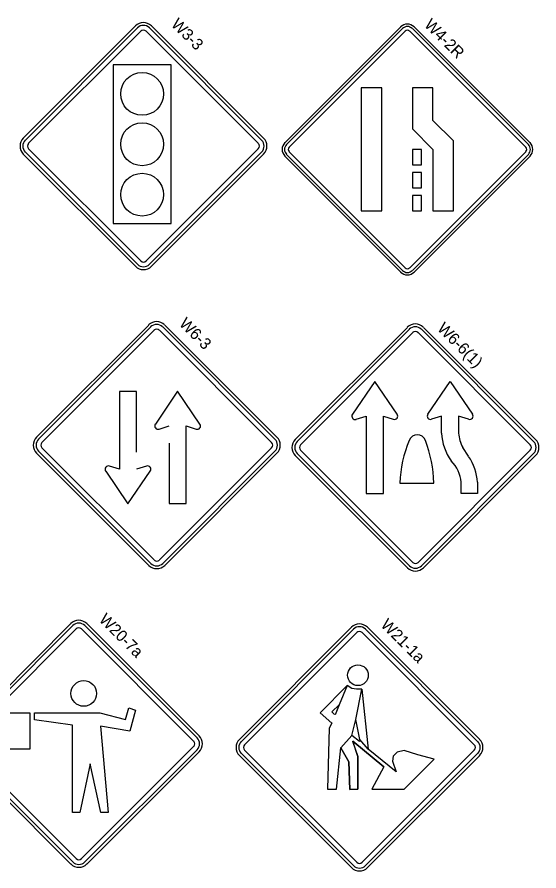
# Model space of a CAD drawing. Extents: x 1531.44 to 1538.58, y 1529.59 to 1539.3.
# Drawn here: x 1535.575 to 1538.294, y 1534.329 to 1538.777 of the extents above; entities that cross this region are included whole.
import ezdxf

# ---------------------------------------------------------------- set-up
doc = ezdxf.new("R2010")
doc.units = 0
for name, color, linetype in [('DETL-LINE', 7, 'Continuous'), ('DETL-NOTE', 7, 'Continuous'), ('SIGN-FACE_E', 7, 'Continuous')]:
    doc.layers.add(name, color=color, linetype=linetype)

msp = doc.modelspace()

# ---------------------------------------------------------------- linework, layer by layer
at = {"layer": 'DETL-LINE'}
for p, q in [((1536.1918, 1538.7309), (1535.6075, 1538.1466)), ((1536.2024, 1538.7212), (1535.618, 1538.136)), ((1536.8492, 1538.136), (1536.2648, 1538.7212)), ((1536.8597, 1538.1466), (1536.2754, 1538.7309)), ((1535.6348, 1538.1193), (1536.22, 1538.7036)), ((1536.2468, 1538.7036), (1536.2472, 1538.7036)), ((1536.8316, 1538.1193), (1536.2472, 1538.7036)), ((1536.2472, 1538.7036), (1536.8316, 1538.1193)), ((1536.2472, 1538.7036), (1536.8316, 1538.1193)), ((1536.377, 1538.5276), (1536.0752, 1538.5276)), ((1536.0752, 1538.5276), (1536.0752, 1537.701)), ((1536.377, 1537.701), (1536.377, 1538.5276)), ((1535.6075, 1538.063), (1536.1918, 1537.4786)), ((1535.618, 1538.0735), (1536.2024, 1537.4892)), ((1536.22, 1537.5068), (1535.6348, 1538.0911)), ((1536.8316, 1538.0911), (1536.2472, 1537.5068)), ((1536.2648, 1537.4892), (1536.8492, 1538.0735)), ((1536.2754, 1537.4786), (1536.8597, 1538.063)), ((1536.0752, 1537.701), (1536.377, 1537.701)), ((1536.2612, 1537.1726), (1535.6768, 1536.5883)), ((1536.2717, 1537.163), (1535.6874, 1536.5778)), ((1536.9185, 1536.5778), (1536.3342, 1537.163)), ((1536.9291, 1536.5883), (1536.3448, 1537.1726)), ((1535.7041, 1536.561), (1536.2893, 1537.1454)), ((1536.3162, 1537.1453), (1536.3166, 1537.1454)), ((1536.9009, 1536.561), (1536.3166, 1537.1454)), ((1536.3166, 1537.1454), (1536.9009, 1536.561)), ((1536.3166, 1537.1454), (1536.9009, 1536.561)), ((1537.609, 1537.1604), (1537.0246, 1536.5761)), ((1537.6195, 1537.1507), (1537.0352, 1536.5655)), ((1537.0519, 1536.5488), (1537.6371, 1537.1331)), ((1537.664, 1537.1331), (1537.6644, 1537.1331)), ((1538.2487, 1536.5488), (1537.6644, 1537.1331)), ((1537.6644, 1537.1331), (1538.2487, 1536.5488)), ((1537.6644, 1537.1331), (1538.2487, 1536.5488)), ((1538.2663, 1536.5655), (1537.682, 1537.1507)), ((1538.2769, 1536.5761), (1537.6926, 1537.1604)), ((1537.4385, 1536.8785), (1537.3223, 1536.7078)), ((1537.5555, 1536.7078), (1537.4385, 1536.8785)), ((1537.7148, 1536.7078), (1537.831, 1536.8785)), ((1537.831, 1536.8785), (1537.948, 1536.7078)), ((1536.1079, 1536.8257), (1536.1079, 1536.5107)), ((1536.1977, 1536.8257), (1536.1079, 1536.8257)), ((1536.1977, 1536.5107), (1536.1977, 1536.8257)), ((1536.4115, 1536.8275), (1536.2954, 1536.6568)), ((1536.5277, 1536.6568), (1536.4115, 1536.8275)), ((1537.3426, 1536.6814), (1537.3945, 1536.6981)), ((1537.3945, 1536.6981), (1537.3945, 1536.6092)), ((1537.4834, 1536.6981), (1537.5353, 1536.6814)), ((1537.4834, 1536.6092), (1537.4834, 1536.6981)), ((1537.787, 1536.6981), (1537.735, 1536.6814)), ((1537.787, 1536.6092), (1537.787, 1536.6981)), ((1537.9278, 1536.6814), (1537.8758, 1536.6981)), ((1537.8758, 1536.6981), (1537.8758, 1536.6092)), ((1536.3147, 1536.6304), (1536.3666, 1536.6471)), ((1536.4564, 1536.5573), (1536.4564, 1536.6471)), ((1536.4564, 1536.6471), (1536.5083, 1536.6304)), ((1537.3945, 1536.6092), (1537.3945, 1536.2942)), ((1537.4834, 1536.2942), (1537.4834, 1536.6092)), ((1536.3666, 1536.5573), (1536.3666, 1536.2423)), ((1536.4564, 1536.2423), (1536.4564, 1536.5573)), ((1535.6768, 1536.5047), (1536.2612, 1535.9204)), ((1535.6874, 1536.5153), (1536.2717, 1535.931)), ((1536.2893, 1535.9486), (1535.7041, 1536.5329)), ((1536.1079, 1536.5107), (1536.1079, 1536.4209)), ((1536.9009, 1536.5329), (1536.3166, 1535.9486)), ((1536.3342, 1535.931), (1536.9185, 1536.5153)), ((1536.3448, 1535.9204), (1536.9291, 1536.5047)), ((1537.0352, 1536.503), (1537.6195, 1535.9187)), ((1537.6371, 1535.9363), (1537.0519, 1536.5206)), ((1538.2487, 1536.5206), (1537.6644, 1535.9363)), ((1537.682, 1535.9187), (1538.2663, 1536.503)), ((1537.9278, 1536.4887), (1537.8978, 1536.5353)), ((1537.0246, 1536.4925), (1537.609, 1535.9082)), ((1537.6926, 1535.9082), (1538.2769, 1536.4925)), ((1536.0366, 1536.4112), (1536.1528, 1536.2405)), ((1536.1079, 1536.4209), (1536.056, 1536.4376)), ((1536.1528, 1536.2405), (1536.269, 1536.4112)), ((1536.2496, 1536.4376), (1536.1977, 1536.4209)), ((1537.5687, 1536.3488), (1537.7465, 1536.3488)), ((1537.889, 1536.2951), (1537.889, 1536.3532)), ((1537.9744, 1536.3532), (1537.9744, 1536.2951)), ((1537.3945, 1536.2942), (1537.4834, 1536.2942)), ((1537.9744, 1536.2951), (1537.889, 1536.2951)), ((1536.3666, 1536.2423), (1536.4564, 1536.2423)), ((1535.8551, 1535.6169), (1535.2708, 1535.0326)), ((1535.8657, 1535.6072), (1535.2814, 1535.022)), ((1536.5125, 1535.022), (1535.9282, 1535.6072)), ((1536.523, 1535.0326), (1535.9387, 1535.6169)), ((1535.2981, 1535.0053), (1535.8833, 1535.5896)), ((1535.9101, 1535.5896), (1535.9106, 1535.5896)), ((1536.4949, 1535.0053), (1535.9106, 1535.5896)), ((1535.9106, 1535.5896), (1536.4949, 1535.0053)), ((1535.9106, 1535.5896), (1536.4949, 1535.0053)), ((1537.3175, 1535.598), (1536.7332, 1535.0136)), ((1537.328, 1535.5883), (1536.7437, 1535.0031)), ((1536.7604, 1534.9864), (1537.3456, 1535.5707)), ((1537.3725, 1535.5706), (1537.3729, 1535.5707)), ((1537.9572, 1534.9864), (1537.3729, 1535.5707)), ((1537.3729, 1535.5707), (1537.9572, 1534.9864)), ((1537.3729, 1535.5707), (1537.9572, 1534.9864)), ((1537.9748, 1535.0031), (1537.3905, 1535.5883)), ((1537.9854, 1535.0136), (1537.4011, 1535.598)), ((1537.1547, 1535.1524), (1537.2942, 1535.295)), ((1537.1547, 1535.1524), (1537.2942, 1535.295)), ((1537.2942, 1535.295), (1537.2535, 1535.1934)), ((1537.3194, 1535.2788), (1537.2942, 1535.295)), ((1537.344, 1535.2751), (1537.3194, 1535.2788)), ((1537.3406, 1535.117), (1537.3716, 1535.2751)), ((1537.3406, 1535.117), (1537.3716, 1535.2751)), ((1537.3716, 1535.2751), (1537.344, 1535.2751)), ((1537.3716, 1535.2751), (1537.4052, 1534.9634)), ((1536.1398, 1535.1174), (1536.1564, 1535.1781)), ((1536.1398, 1535.1174), (1536.1564, 1535.1781)), ((1536.1564, 1535.1781), (1536.1919, 1535.1655)), ((1536.1564, 1535.1781), (1536.1919, 1535.1655)), ((1536.1919, 1535.1655), (1536.1622, 1535.0562)), ((1536.1919, 1535.1655), (1536.1622, 1535.0562)), ((1537.2535, 1535.1934), (1537.2148, 1535.1569)), ((1537.2148, 1535.1569), (1537.2535, 1535.1934)), ((1537.2535, 1535.1934), (1537.2148, 1535.1569)), ((1537.2535, 1535.1934), (1537.2322, 1535.1414)), ((1535.4896, 1535.1523), (1535.6407, 1535.1523)), ((1535.6407, 1535.1523), (1535.6407, 1534.9628)), ((1535.6658, 1535.1151), (1535.6658, 1535.1529)), ((1535.6658, 1535.1529), (1536.0065, 1535.1529)), ((1535.6658, 1535.1529), (1536.0065, 1535.1529)), ((1535.6658, 1535.1151), (1535.6658, 1535.1529)), ((1535.8634, 1535.0876), (1535.6658, 1535.1151)), ((1535.8634, 1535.0876), (1535.6658, 1535.1151)), ((1536.0065, 1535.1529), (1536.1398, 1535.1174)), ((1536.0065, 1535.1529), (1536.1398, 1535.1174)), ((1537.1547, 1535.1524), (1537.2154, 1535.0981)), ((1537.229, 1535.1433), (1537.2148, 1535.1569)), ((1537.3194, 1535.0343), (1537.3406, 1535.117)), ((1537.3616, 1535.0136), (1537.3406, 1535.117)), ((1535.8634, 1534.6337), (1535.8634, 1535.0876)), ((1535.8634, 1534.6337), (1535.8634, 1535.0876)), ((1536.1622, 1535.0562), (1536.0099, 1535.0831)), ((1536.0099, 1535.0831), (1536.05, 1534.6337)), ((1536.1622, 1535.0562), (1536.0099, 1535.0831)), ((1536.0099, 1535.0831), (1536.05, 1534.6337)), ((1537.3596, 1535.0025), (1537.3194, 1535.0343)), ((1537.4856, 1534.8704), (1537.3236, 1535.0054)), ((1537.3616, 1535.0136), (1537.3596, 1535.0025)), ((1535.2708, 1534.949), (1535.8551, 1534.3646)), ((1535.2814, 1534.9595), (1535.8657, 1534.3752)), ((1535.8833, 1534.3928), (1535.2981, 1534.9771)), ((1535.6407, 1534.9628), (1535.4896, 1534.9628)), ((1536.4949, 1534.9771), (1535.9106, 1534.3928)), ((1535.9282, 1534.3752), (1536.5125, 1534.9595)), ((1535.9387, 1534.3646), (1536.523, 1534.949)), ((1536.7437, 1534.9406), (1537.328, 1534.3563)), ((1537.3456, 1534.3739), (1536.7604, 1534.9582)), ((1537.2398, 1534.7541), (1537.2621, 1534.9694)), ((1537.9572, 1534.9582), (1537.3729, 1534.3739)), ((1537.3905, 1534.3563), (1537.9748, 1534.9406)), ((1537.5497, 1534.8444), (1537.4052, 1534.9634)), ((1537.5549, 1534.9474), (1537.535, 1534.9264)), ((1537.5927, 1534.9552), (1537.5549, 1534.9474)), ((1537.6639, 1534.9337), (1537.5927, 1534.9552)), ((1536.7332, 1534.93), (1537.3175, 1534.3457)), ((1537.4011, 1534.3457), (1537.9854, 1534.93)), ((1537.535, 1534.9264), (1537.5313, 1534.9001)), ((1537.5313, 1534.9001), (1537.5497, 1534.8444)), ((1537.5927, 1534.7546), (1537.7476, 1534.9111)), ((1537.7476, 1534.9111), (1537.6639, 1534.9337)), ((1535.9566, 1534.8867), (1535.9011, 1534.6337)), ((1535.9566, 1534.8867), (1535.9011, 1534.6337)), ((1536.0122, 1534.6337), (1535.9566, 1534.8867)), ((1536.0122, 1534.6337), (1535.9566, 1534.8867)), ((1537.4856, 1534.8704), (1537.4234, 1534.7541)), ((1537.4234, 1534.7541), (1537.5927, 1534.7546)), ((1535.9011, 1534.6337), (1535.8634, 1534.6337)), ((1535.9011, 1534.6337), (1535.8634, 1534.6337)), ((1536.05, 1534.6337), (1536.0122, 1534.6337)), ((1536.05, 1534.6337), (1536.0122, 1534.6337))]:
    msp.add_line(p, q, dxfattribs=at)
for points in [[(1537.2154, 1535.0999), (1537.2141, 1535.0957), (1537.201, 1535.0732), (1537.1928, 1534.7541), (1537.2398, 1534.7541)], [(1537.4052, 1534.9634), (1537.3616, 1535.0136), (1537.3606, 1535.008), (1537.3596, 1535.0025), (1537.3194, 1535.0343), (1537.2621, 1534.9694), (1537.3036, 1534.8972), (1537.3081, 1534.753), (1537.3501, 1534.7541), (1537.3509, 1534.9243), (1537.3236, 1535.0054), (1537.4856, 1534.8704)], [(1537.3222, 1535.0046), (1537.3509, 1534.9243), (1537.3501, 1534.7541), (1537.3081, 1534.753), (1537.3036, 1534.8972), (1537.2621, 1534.9694), (1537.2621, 1534.972)]]:
    msp.add_lwpolyline(points, dxfattribs=at)
for centre, radius in [((1536.2262, 1538.3766), 0.1115), ((1536.2262, 1538.1142), 0.1115), ((1536.2262, 1537.8518), 0.1115), ((1537.3512, 1535.3482), 0.0539), ((1535.9223, 1535.2531), 0.0668)]:
    msp.add_circle(centre, radius, dxfattribs=at)
for centre, radius, start, end in [((1536.2329, 1538.6896), 0.059, 45, 135), ((1536.2329, 1538.6896), 0.0443, 45, 135), ((1536.2329, 1538.6896), 0.0197, 45, 135), ((1535.6492, 1538.1048), 0.059, 135, 225), ((1536.8179, 1538.1051), 0.059, 315, 45), ((1535.649, 1538.1051), 0.0443, 135, 225), ((1535.649, 1538.1051), 0.0197, 135, 225), ((1536.8179, 1538.1051), 0.0197, 315, 45), ((1536.8179, 1538.1051), 0.0443, 315, 45), ((1536.2335, 1537.5206), 0.059, 225, 315), ((1536.2335, 1537.5206), 0.0443, 225, 315), ((1536.2335, 1537.5206), 0.0197, 225, 315), ((1536.3022, 1537.1314), 0.059, 45, 135), ((1536.3022, 1537.1314), 0.0443, 45, 135), ((1537.65, 1537.1192), 0.059, 45, 135), ((1537.65, 1537.1192), 0.0443, 45, 135), ((1536.3022, 1537.1314), 0.0197, 45, 135), ((1537.65, 1537.1192), 0.0197, 45, 135), ((1537.3368, 1536.6979), 0.0175, 145.7397, 288), ((1537.5407, 1536.6981), 0.0175, 252, 34.2603), ((1537.7295, 1536.6981), 0.0175, 145.7397, 288), ((1537.9332, 1536.6981), 0.0175, 252, 34.2603), ((1536.3097, 1536.6468), 0.0175, 145.7397, 288), ((1536.5134, 1536.6468), 0.0175, 252, 34.2603), ((1535.7186, 1536.5466), 0.059, 135, 225), ((1536.8873, 1536.5468), 0.059, 315, 45), ((1537.6605, 1536.5564), 0.0446, 20.3641, 159.6359), ((1538.0539, 1536.6209), 0.2674, 182.5554, 215.8093), ((1538.0539, 1536.6209), 0.1784, 183.8322, 208.8162), ((1535.7184, 1536.5468), 0.0443, 135, 225), ((1535.7184, 1536.5468), 0.0197, 135, 225), ((1536.8873, 1536.5468), 0.0197, 315, 45), ((1536.8873, 1536.5468), 0.0443, 315, 45), ((1537.0664, 1536.5344), 0.059, 135, 225), ((1537.0662, 1536.5346), 0.0443, 135, 225), ((1537.0662, 1536.5346), 0.0197, 135, 225), ((1538.2363, 1536.3159), 0.6685, 157.4833, 177.1559), ((1537.0786, 1536.3313), 0.6685, 1.524, 21.0959), ((1538.2351, 1536.5346), 0.0197, 315, 45), ((1538.2351, 1536.5346), 0.0443, 315, 45), ((1538.2351, 1536.5346), 0.059, 315, 45), ((1537.7097, 1536.3377), 0.1797, 4.968, 44.8693), ((1537.7097, 1536.3377), 0.265, 3.3657, 34.6128), ((1536.0509, 1536.4212), 0.0175, 72, 214.2603), ((1536.2547, 1536.4212), 0.0175, 325.7397, 108), ((1536.3028, 1535.9624), 0.059, 225, 315), ((1536.3028, 1535.9624), 0.0443, 225, 315), ((1536.3028, 1535.9624), 0.0197, 225, 315), ((1537.6506, 1535.9501), 0.0443, 225, 315), ((1537.6506, 1535.9501), 0.0197, 225, 315), ((1537.6506, 1535.9501), 0.059, 225, 315), ((1535.8962, 1535.5756), 0.059, 45, 135), ((1535.8962, 1535.5756), 0.0443, 45, 135), ((1537.3586, 1535.5567), 0.059, 45, 135), ((1535.8962, 1535.5756), 0.0197, 45, 135), ((1537.3586, 1535.5567), 0.0443, 45, 135), ((1537.3586, 1535.5567), 0.0197, 45, 135), ((1536.4813, 1534.9911), 0.059, 315, 45), ((1536.4813, 1534.9911), 0.0197, 315, 45), ((1536.4813, 1534.9911), 0.0443, 315, 45), ((1536.7749, 1534.9719), 0.059, 135, 225), ((1536.7747, 1534.9722), 0.0443, 135, 225), ((1536.7747, 1534.9722), 0.0197, 135, 225), ((1537.9436, 1534.9722), 0.0197, 315, 45), ((1537.9436, 1534.9722), 0.0443, 315, 45), ((1537.9436, 1534.9722), 0.059, 315, 45), ((1535.8968, 1534.4066), 0.059, 225, 315), ((1535.8968, 1534.4066), 0.0443, 225, 315), ((1535.8968, 1534.4066), 0.0197, 225, 315), ((1537.3592, 1534.3877), 0.0197, 225, 315), ((1537.3592, 1534.3877), 0.059, 225, 315), ((1537.3592, 1534.3877), 0.0443, 225, 315)]:
    msp.add_arc(centre, radius, start, end, dxfattribs=at)
at = {"layer": 'SIGN-FACE_E'}
for p, q in [((1536.9705, 1538.1226), (1537.5737, 1538.7258)), ((1537.6435, 1538.7258), (1538.248, 1538.1226)), ((1536.9794, 1538.1137), (1537.5826, 1538.7169)), ((1536.9934, 1538.0998), (1537.5965, 1538.703)), ((1537.6207, 1538.703), (1538.2251, 1538.0998)), ((1537.6346, 1538.7169), (1538.2391, 1538.1137)), ((1537.5737, 1537.4484), (1536.9705, 1538.0528)), ((1537.5826, 1537.4572), (1536.9794, 1538.0617)), ((1537.5965, 1537.4712), (1536.9934, 1538.0757)), ((1538.2251, 1538.0757), (1537.6207, 1537.4712)), ((1538.2391, 1538.0617), (1537.6346, 1537.4572)), ((1538.248, 1538.0528), (1537.6435, 1537.4484))]:
    msp.add_line(p, q, dxfattribs=at)
for points in [[(1537.4753, 1538.4077), (1537.3686, 1538.4077), (1537.3686, 1537.7677), (1537.4753, 1537.7677), (1537.4753, 1538.4077)], [(1537.8486, 1538.1319), (1537.7419, 1538.2386), (1537.7419, 1538.4077), (1537.6353, 1538.4077), (1537.6353, 1538.1944), (1537.7419, 1538.0877), (1537.7419, 1537.7677), (1537.8486, 1537.7677), (1537.8486, 1538.1319)], [(1537.6353, 1538.0077), (1537.6819, 1538.0077), (1537.6819, 1538.0877), (1537.6353, 1538.0877), (1537.6353, 1538.0077)], [(1537.6353, 1537.8877), (1537.6819, 1537.8877), (1537.6819, 1537.9677), (1537.6353, 1537.9677), (1537.6353, 1537.8877)], [(1537.6353, 1537.7677), (1537.6819, 1537.7677), (1537.6819, 1537.8477), (1537.6353, 1537.8477), (1537.6353, 1537.7677)]]:
    msp.add_lwpolyline(points, dxfattribs=at)
for centre, radius, start, end in [((1537.6086, 1538.6906), 0.0496, 45.06, 135), ((1537.6086, 1538.6913), 0.0365, 45.06, 135), ((1537.6086, 1538.6916), 0.0165, 45.06, 135), ((1537.0057, 1538.0877), 0.0496, 135, 224.9399), ((1537.005, 1538.0877), 0.0365, 135, 224.9399), ((1537.0047, 1538.0877), 0.0165, 135, 224.9399), ((1538.2138, 1538.0877), 0.0165, 315, 45.0601), ((1538.2135, 1538.0877), 0.0365, 315, 45.0601), ((1538.2127, 1538.0877), 0.0496, 315, 45.0601), ((1537.6086, 1537.4836), 0.0496, 224.94, 315), ((1537.6086, 1537.4828), 0.0365, 224.94, 315), ((1537.6086, 1537.4825), 0.0165, 224.94, 315)]:
    msp.add_arc(centre, radius, start, end, dxfattribs=at)

# ---------------------------------------------------------------- texts
at = {"layer": 'DETL-NOTE'}
for s, p in [('W3-3', (1536.3739, 1538.7348)), ('W4-2R', (1537.6929, 1538.7324)), ('W6-3', (1536.4156, 1537.175)), ('W6-6(1)', (1537.7604, 1537.1501)), ('W20-7a', (1535.9979, 1535.6336)), ('W21-1a', (1537.4658, 1535.6064))]:
    msp.add_text(s, height=0.06, rotation=315, dxfattribs=at).set_placement(p)

doc.saveas('drawing.dxf')
